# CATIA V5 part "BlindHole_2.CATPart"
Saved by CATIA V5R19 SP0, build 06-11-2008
Bounding box of the stored display mesh (mm): x -6.991 to 6.991, y -6.895 to 6.895, z -2.887 to 20
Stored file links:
  C:\Program Files\Dassault Systemes\Power Feature\SampleData\GeneralData\Catalog\Udfs\BlindHole_2.CATPart
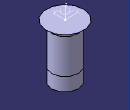
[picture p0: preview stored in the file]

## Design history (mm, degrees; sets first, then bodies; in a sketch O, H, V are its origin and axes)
Body1 (main body)
  Plane1 "InsertDirection": type Offset, Offset 20, RefPlane xy-plane
  Point1 "InsertPoint": type OnPlane, Support Plane1, Direction (1, 0, 0), H 0, V 0
  Body2 "UDF_Body"
    AxisSystem1 "MainAxisSystem": origin (0, 0, 20), X (-1, 0, 0), Y (0, -1, 0), Z (0, 0, 1)
    Sketch1 "MainProfileSketch" on ZX plane of AxisSystem1, origin (0, 0, 20), H (1, 0, 0), V (0, 0, 1)
      axis line L1 (0, 0) -> (0, -22.8868)
      point P2 (0, -22.8868)
      line L2 (0, -22.8868) -> (5, -20)
      point P3 (5, -20)
      line L3 (5, -20) -> (5, -15)
      line L4 (5, -2) -> (7, 0)
      point P4 (7, 0)
      line L5 (7, 0) -> (7, 0)
      line L6 (7, 0) -> (7, 0)
      line L7 (7, 0) -> (0, 0)
      point P7 (-5, -20)
      point P8 (0, -22.8868)
      construction line L8 (0, -22.8868) -> (-5, -20)
      construction line L9 (7, 0) -> (0, 0)
      reference projected line E1 through (0, 0) direction (-1, 0) from edge [XY plane of AxisSystem1 | ZX plane of AxisSystem1]
      reference projected line E2 through (0, 0) direction (-1, 0) from edge [XY plane of AxisSystem1 | ZX plane of AxisSystem1]
      reference projected line E3 through (0, 0) direction (0, 1) from edge [ZX plane of AxisSystem1 | YZ plane of AxisSystem1]
      point P9 (5, -15)
      reference projected line E4 through (0, 0) direction (-1, 0) from edge [XY plane of AxisSystem1 | ZX plane of AxisSystem1]
      point P10 (5, -2)
      point P11 (-7, 0)
      point P12 (-5, -2)
      construction line L10 (-5, -2) -> (-7, 0)
      line L11 (5, -15) -> (5, -2)
      reference projected line E5 through (0, 0) direction (-1, 0) from edge [XY plane of AxisSystem1 | ZX plane of AxisSystem1]
      point P13 (5, -2)
      reference projected line E6 through (0, 0) direction (-1, 0) from edge [XY plane of AxisSystem1 | ZX plane of AxisSystem1]
      point P14 (0, 30)
      point P15 (5, 25)
      point P16 (5, -15)
      point P17 (5, -15)
      line L12 (5, -15) -> (5, -15)
      angle L4 L10 = 90
      angle L2 L8 = 120
      distance E1 P3 = 20
      length L9 = 7 {= sqrt((Body2.AS_H * Body2.AS_H ) + ((Groove1.top_width / 2 + Groove1.AS_ZR ) * (Groove1.top_width / 2 + Groove1.AS_ZR )))}
      angle L9 L5 = 0 {= atan(Body2.AS_H / (Groove1.top_width / 2 + Groove1.AS_ZR ))}
      distance E4 P17 = 15
      "Radius" L11 L1 = 5 {= Body2.DB / 2}
      distance E6 P10 = 2
      distance O P14 = 30
      distance P10 P14 V = 32 {= Sketch1.distance(O P14) + Body2.F}
      distance O P15 V = 25
      distance P16 P15 = 40
      distance P9 P15 = 40
      distance P17 P15 = 40 {= Sketch1.distance(O P15 V) + Body2.TP}
      "Radius" L3 L1 = 5 {= Sketch1.Radius(L11 L1)}
      coincidence: E5 L5, L1 E3, P13 L11, P13 P10, P14 L1, P15 L11, P17 L11
      symmetry: P3 P7 L1, P2 P8 L1, L2 L8 L1, P4 P11 L1, P10 P12 L1, L4 L10 L1
      perpendicularity: L1 L7, E2 L6
    Groove1 "MainGroove": profile Sketch1, axis Sketch1.L1, angle 360
  Assemble1 "UDF_Assemble": tool Body2
Body3 "UDF_Body"
  AxisSystem2 "MainAxisSystem": origin (0, 0, 20), X (-1, 0, 0), Y (0, -1, 0), Z (0, 0, 1)
  Sketch2 "MainProfileSketch" on ZX plane of AxisSystem2, origin (0, 0, 20), H (1, 0, 0), V (0, 0, 1)
    axis line L1 (0, 0) -> (0, -22.8868)
    point P2 (0, -22.8868)
    line L2 (0, -22.8868) -> (5, -20)
    point P3 (5, -20)
    line L3 (5, -20) -> (5, -15)
    line L4 (5, -2) -> (7, 0)
    point P4 (7, 0)
    line L5 (7, 0) -> (7, 0)
    line L6 (7, 0) -> (7, 0)
    line L7 (7, 0) -> (0, 0)
    point P7 (-5, -20)
    point P8 (0, -22.8868)
    construction line L8 (0, -22.8868) -> (-5, -20)
    construction line L9 (7, 0) -> (0, 0)
    reference projected line E1 through (0, 0) direction (-1, 0) from edge [XY plane of AxisSystem2 | ZX plane of AxisSystem2]
    reference projected line E2 through (0, 0) direction (-1, 0) from edge [XY plane of AxisSystem2 | ZX plane of AxisSystem2]
    reference projected line E3 through (0, 0) direction (0, 1) from edge [ZX plane of AxisSystem2 | YZ plane of AxisSystem2]
    point P9 (5, -15)
    reference projected line E4 through (0, 0) direction (-1, 0) from edge [XY plane of AxisSystem2 | ZX plane of AxisSystem2]
    point P10 (5, -2)
    point P11 (-7, 0)
    point P12 (-5, -2)
    construction line L10 (-5, -2) -> (-7, 0)
    line L11 (5, -15) -> (5, -2)
    reference projected line E5 through (0, 0) direction (-1, 0) from edge [XY plane of AxisSystem2 | ZX plane of AxisSystem2]
    point P13 (5, -2)
    reference projected line E6 through (0, 0) direction (-1, 0) from edge [XY plane of AxisSystem2 | ZX plane of AxisSystem2]
    point P14 (0, 30)
    point P15 (5, 25)
    point P16 (5, -15)
    point P17 (5, -15)
    line L12 (5, -15) -> (5, -15)
    angle L4 L10 = 90
    angle L2 L8 = 120
    distance E1 P3 = 20
    length L9 = 7 {= sqrt((Body3.AS_H * Body3.AS_H ) + ((Groove2.top_width / 2 + Groove2.AS_ZR ) * (Groove2.top_width / 2 + Groove2.AS_ZR )))}
    angle L9 L5 = 0 {= atan(Body3.AS_H / (Groove2.top_width / 2 + Groove2.AS_ZR ))}
    distance E4 P17 = 15
    "UIHidden_zDB" L11 L1 = 5 {= Body3.DB2 / 2}
    distance E6 P10 = 2
    distance O P14 = 30
    distance P10 P14 V = 32 {= Sketch2.distance(O P14) + Body3.F}
    distance O P15 V = 25
    distance P16 P15 = 40
    distance P9 P15 = 40
    distance P17 P15 = 40 {= Sketch2.distance(O P15 V) + Body3.TP}
    "Radius" L3 L1 = 5 {= Sketch2.UIHidden_zDB(L11 L1)}
    coincidence: E5 L5, L1 E3, P13 L11, P13 P10, P14 L1, P15 L11, P17 L11
    symmetry: P3 P7 L1, P2 P8 L1, L2 L8 L1, P4 P11 L1, P10 P12 L1, L4 L10 L1
    perpendicularity: L1 L7, E2 L6
  Groove2 "MainGroove": profile Sketch2, axis Sketch2.L1, angle 360
Relations
  rule:
  Body2.W = Sketch1.angle(L4 L10)
  Body2.T = Sketch1.distance(E1 P3)
  Body2.SW = Sketch1.angle(L2 L8)
  rule "AS_ZR":
    /*Rule created by AKNOPP 22.05.2006*/
    Groove1.AS_ZR = Body2.AS_D - Groove1.top_width
    if (Body2.AS_D == 0mm)
    {
    	Groove1.AS_ZR = 0mm
    }
    else
    {
    	Groove1.AS_ZR = (Body2.AS_D / 2) - (Groove1.top_width / 2)
    }
  Groove1.top_width = (Sketch1.Radius(L11 L1) * 2) + (2 * tan(Sketch1.angle(L4 L10) / 2) *Sketch1.distance(E6 P10))
  Body3.W = Sketch2.angle(L4 L10)
  Body3.T = Sketch2.distance(E1 P3)
  Body3.SW = Sketch2.angle(L2 L8)
  Groove2.top_width = (Sketch2.UIHidden_zDB(L11 L1) * 2) + (2 * tan(Sketch2.angle(L4 L10) / 2) *Sketch2.distance(E6 P10))
  rule "AS_ZR":
    /*Rule created by AKNOPP 22.05.2006*/
    Groove2.AS_ZR = Body3.AS_D - Groove2.top_width
    if (Body3.AS_D == 0mm)
    {
    	Groove2.AS_ZR = 0mm
    }
    else
    {
    	Groove2.AS_ZR = (Body3.AS_D / 2) - (Groove2.top_width / 2)
    }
